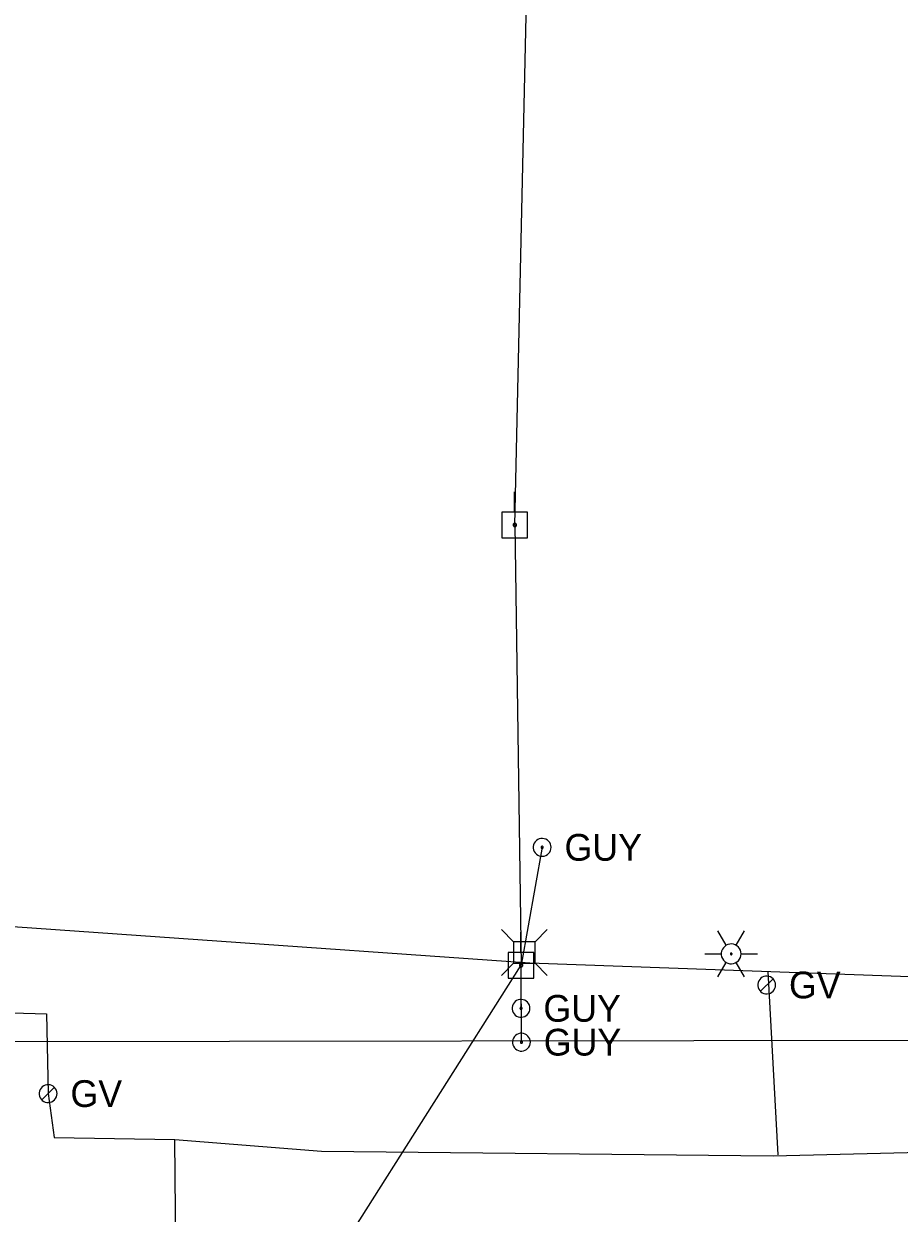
# Model space of a CAD drawing. Extents: x 596028 to 606371, y 330010 to 403088.
# Drawn here: x 604484.3 to 604610.3, y 349950.1 to 350121.3 of the extents above; entities that cross this region are included whole.
import ezdxf

# ---------------------------------------------------------------- set-up
doc = ezdxf.new("R2010")
doc.units = 0
for name, color, linetype in [('E_LTG', 7, 'Continuous'), ('E_UTL_EGuyWire', 7, 'Continuous'), ('E_UTL_EPowerPole', 7, 'Continuous'), ('E_UTL_G', 7, 'Continuous'), ('E_UTL_G_UG', 7, 'Continuous'), ('E_UTL_Overhead', 7, 'Continuous'), ('E_UTL_SAN_UG', 7, 'Continuous'), ('E_UTL_T', 7, 'Continuous')]:
    doc.layers.add(name, color=color, linetype=linetype)

# ---------------------------------------------------------------- blocks, each defined once
blk = doc.blocks.new('ACAD_PROXY_ENTITY_15')
at = {"layer": 'E_LTG'}
for points in [[(1843663.8, 1030159.59), (1843660.17, 1030165.87)], [(1843668.16, 1030159.59), (1843671.79, 1030165.87)], [(1843670.34, 1030155.82), (1843670.26, 1030156.64), (1843670.02, 1030157.44), (1843669.64, 1030158.17), (1843669.13, 1030158.82), (1843668.51, 1030159.36), (1843667.79, 1030159.78), (1843667.01, 1030160.05), (1843666.19, 1030160.17), (1843665.36, 1030160.13), (1843664.56, 1030159.93), (1843663.8, 1030159.59), (1843663.13, 1030159.11), (1843662.56, 1030158.51), (1843662.11, 1030157.81), (1843661.8, 1030157.04), (1843661.64, 1030156.23), (1843661.64, 1030155.4), (1843661.8, 1030154.59), (1843662.11, 1030153.82), (1843662.56, 1030153.12), (1843663.13, 1030152.52), (1843663.8, 1030152.04), (1843664.56, 1030151.7), (1843665.36, 1030151.51), (1843666.19, 1030151.47), (1843667.01, 1030151.58), (1843667.79, 1030151.85), (1843668.51, 1030152.27), (1843669.13, 1030152.81), (1843669.64, 1030153.46), (1843670.02, 1030154.2), (1843670.26, 1030154.99), (1843670.34, 1030155.82)], [(1843670.34, 1030155.82), (1843670.26, 1030156.64), (1843670.02, 1030157.44), (1843669.64, 1030158.17), (1843669.13, 1030158.82), (1843668.51, 1030159.36), (1843667.79, 1030159.78), (1843667.01, 1030160.05), (1843666.19, 1030160.17), (1843665.36, 1030160.13), (1843664.56, 1030159.93), (1843663.8, 1030159.59), (1843663.13, 1030159.11), (1843662.56, 1030158.51), (1843662.11, 1030157.81), (1843661.8, 1030157.04), (1843661.64, 1030156.23), (1843661.64, 1030155.4), (1843661.8, 1030154.59), (1843662.11, 1030153.82), (1843662.56, 1030153.12), (1843663.13, 1030152.52), (1843663.8, 1030152.04), (1843664.56, 1030151.7), (1843665.36, 1030151.51), (1843666.19, 1030151.47), (1843667.01, 1030151.58), (1843667.79, 1030151.85), (1843668.51, 1030152.27), (1843669.13, 1030152.81), (1843669.64, 1030153.46), (1843670.02, 1030154.2), (1843670.26, 1030154.99), (1843670.34, 1030155.82)], [(1843670.34, 1030155.82), (1843670.26, 1030156.64), (1843670.02, 1030157.44), (1843669.64, 1030158.17), (1843669.13, 1030158.82), (1843668.51, 1030159.36), (1843667.79, 1030159.78), (1843667.01, 1030160.05), (1843666.19, 1030160.17), (1843665.36, 1030160.13), (1843664.56, 1030159.93), (1843663.8, 1030159.59), (1843663.13, 1030159.11), (1843662.56, 1030158.51), (1843662.11, 1030157.81), (1843661.8, 1030157.04), (1843661.64, 1030156.23), (1843661.64, 1030155.4), (1843661.8, 1030154.59), (1843662.11, 1030153.82), (1843662.56, 1030153.12), (1843663.13, 1030152.52), (1843663.8, 1030152.04), (1843664.56, 1030151.7), (1843665.36, 1030151.51), (1843666.19, 1030151.47), (1843667.01, 1030151.58), (1843667.79, 1030151.85), (1843668.51, 1030152.27), (1843669.13, 1030152.81), (1843669.64, 1030153.46), (1843670.02, 1030154.2), (1843670.26, 1030154.99), (1843670.34, 1030155.82)], [(1843654.37, 1030155.82), (1843661.62, 1030155.82)], [(1843660.17, 1030145.76), (1843663.8, 1030152.04)], [(1843666.34, 1030155.82), (1843666.34, 1030155.88), (1843666.32, 1030155.95), (1843666.29, 1030156.01), (1843666.24, 1030156.07), (1843666.19, 1030156.11), (1843666.13, 1030156.15), (1843666.07, 1030156.17), (1843666, 1030156.18), (1843665.93, 1030156.18), (1843665.86, 1030156.16), (1843665.8, 1030156.13), (1843665.74, 1030156.09), (1843665.69, 1030156.04), (1843665.66, 1030155.98), (1843665.63, 1030155.92), (1843665.62, 1030155.85), (1843665.62, 1030155.78), (1843665.63, 1030155.71), (1843665.66, 1030155.65), (1843665.69, 1030155.59), (1843665.74, 1030155.54), (1843665.8, 1030155.5), (1843665.86, 1030155.47), (1843665.93, 1030155.46), (1843666, 1030155.45), (1843666.07, 1030155.46), (1843666.13, 1030155.49), (1843666.19, 1030155.52), (1843666.24, 1030155.57), (1843666.29, 1030155.62), (1843666.32, 1030155.68), (1843666.34, 1030155.75), (1843666.34, 1030155.82)], [(1843671.79, 1030145.76), (1843668.16, 1030152.04)], [(1843670.34, 1030155.82), (1843677.59, 1030155.82)]]:
    blk.add_lwpolyline(points, dxfattribs=at)

msp = doc.modelspace()

# ---------------------------------------------------------------- linework, layer by layer
at = {"layer": 'E_UTL_EGuyWire'}
for p in [(604558.91, 350002.78), (604555.87, 349979.6), (604555.92, 349974.73)]:
    msp.add_line(p, (604555.88, 349985.8), dxfattribs=at)
for points in [[(604560.19, 350002.78), (604560.17, 350003.02), (604560.1, 350003.25), (604559.99, 350003.47), (604559.84, 350003.66), (604559.65, 350003.82), (604559.44, 350003.94), (604559.21, 350004.02), (604558.97, 350004.06), (604558.72, 350004.05), (604558.49, 350003.99), (604558.27, 350003.89), (604558.07, 350003.74), (604557.9, 350003.57), (604557.77, 350003.36), (604557.68, 350003.14), (604557.63, 350002.9), (604557.63, 350002.65), (604557.68, 350002.41), (604557.77, 350002.19), (604557.9, 350001.98), (604558.07, 350001.81), (604558.27, 350001.66), (604558.49, 350001.56), (604558.72, 350001.5), (604558.97, 350001.49), (604559.21, 350001.53), (604559.44, 350001.61), (604559.65, 350001.73), (604559.84, 350001.89), (604559.99, 350002.08), (604560.1, 350002.3), (604560.17, 350002.53), (604560.19, 350002.78)], [(604559.07, 350002.78), (604559.06, 350002.81), (604559.06, 350002.83), (604559.04, 350002.86), (604559.02, 350002.89), (604559, 350002.91), (604558.97, 350002.92), (604558.94, 350002.93), (604558.91, 350002.94), (604558.88, 350002.93), (604558.85, 350002.93), (604558.83, 350002.91), (604558.8, 350002.9), (604558.78, 350002.87), (604558.76, 350002.85), (604558.75, 350002.82), (604558.75, 350002.79), (604558.75, 350002.76), (604558.75, 350002.73), (604558.76, 350002.7), (604558.78, 350002.68), (604558.8, 350002.65), (604558.83, 350002.64), (604558.85, 350002.62), (604558.88, 350002.62), (604558.91, 350002.61), (604558.94, 350002.62), (604558.97, 350002.63), (604559, 350002.64), (604559.02, 350002.66), (604559.04, 350002.69), (604559.06, 350002.72), (604559.06, 350002.74), (604559.07, 350002.78)], [(604557.15, 349979.6), (604557.13, 349979.85), (604557.06, 349980.08), (604556.95, 349980.3), (604556.8, 349980.49), (604556.61, 349980.65), (604556.4, 349980.77), (604556.17, 349980.85), (604555.93, 349980.89), (604555.69, 349980.87), (604555.45, 349980.82), (604555.23, 349980.72), (604555.03, 349980.57), (604554.86, 349980.4), (604554.73, 349980.19), (604554.64, 349979.97), (604554.59, 349979.73), (604554.59, 349979.48), (604554.64, 349979.24), (604554.73, 349979.02), (604554.86, 349978.81), (604555.03, 349978.63), (604555.23, 349978.49), (604555.45, 349978.39), (604555.69, 349978.33), (604555.93, 349978.32), (604556.17, 349978.36), (604556.4, 349978.44), (604556.61, 349978.56), (604556.8, 349978.72), (604556.95, 349978.91), (604557.06, 349979.13), (604557.13, 349979.36), (604557.15, 349979.6)], [(604556.03, 349979.6), (604556.03, 349979.63), (604556.02, 349979.66), (604556, 349979.69), (604555.99, 349979.71), (604555.96, 349979.73), (604555.94, 349979.75), (604555.91, 349979.76), (604555.88, 349979.76), (604555.85, 349979.76), (604555.82, 349979.76), (604555.79, 349979.74), (604555.76, 349979.73), (604555.74, 349979.7), (604555.73, 349979.68), (604555.72, 349979.65), (604555.71, 349979.62), (604555.71, 349979.59), (604555.72, 349979.56), (604555.73, 349979.53), (604555.74, 349979.5), (604555.76, 349979.48), (604555.79, 349979.47), (604555.82, 349979.45), (604555.85, 349979.45), (604555.88, 349979.44), (604555.91, 349979.45), (604555.94, 349979.46), (604555.96, 349979.47), (604555.99, 349979.49), (604556, 349979.52), (604556.02, 349979.54), (604556.03, 349979.57), (604556.03, 349979.6)], [(604557.21, 349974.73), (604557.19, 349974.98), (604557.12, 349975.21), (604557, 349975.43), (604556.85, 349975.62), (604556.67, 349975.78), (604556.46, 349975.9), (604556.23, 349975.98), (604555.99, 349976.02), (604555.74, 349976.01), (604555.51, 349975.95), (604555.28, 349975.85), (604555.08, 349975.7), (604554.92, 349975.53), (604554.78, 349975.32), (604554.69, 349975.1), (604554.65, 349974.86), (604554.65, 349974.61), (604554.69, 349974.37), (604554.78, 349974.15), (604554.92, 349973.94), (604555.08, 349973.77), (604555.28, 349973.62), (604555.51, 349973.52), (604555.74, 349973.46), (604555.99, 349973.45), (604556.23, 349973.49), (604556.46, 349973.57), (604556.67, 349973.69), (604556.85, 349973.85), (604557, 349974.04), (604557.12, 349974.26), (604557.19, 349974.49), (604557.21, 349974.73)], [(604556.09, 349974.73), (604556.08, 349974.77), (604556.07, 349974.79), (604556.06, 349974.82), (604556.04, 349974.85), (604556.02, 349974.87), (604555.99, 349974.88), (604555.96, 349974.89), (604555.93, 349974.9), (604555.9, 349974.89), (604555.87, 349974.89), (604555.84, 349974.87), (604555.82, 349974.86), (604555.8, 349974.83), (604555.78, 349974.81), (604555.77, 349974.78), (604555.77, 349974.75), (604555.77, 349974.72), (604555.77, 349974.69), (604555.78, 349974.66), (604555.8, 349974.64), (604555.82, 349974.61), (604555.84, 349974.6), (604555.87, 349974.58), (604555.9, 349974.58), (604555.93, 349974.57), (604555.96, 349974.58), (604555.99, 349974.59), (604556.02, 349974.6), (604556.04, 349974.62), (604556.06, 349974.65), (604556.07, 349974.68), (604556.08, 349974.7), (604556.09, 349974.73)]]:
    msp.add_lwpolyline(points, dxfattribs=at)
at = {"layer": 'E_UTL_EPowerPole'}
for points in [[(604554.93, 350051.02), (604554.93, 350053.93)], [(604556.78, 350051.02), (604553.09, 350051.02)], [(604553.09, 350051.02), (604553.09, 350047.33)], [(604556.78, 350047.33), (604556.78, 350051.02)], [(604555.2, 350049.17), (604555.2, 350049.22), (604555.19, 350049.26), (604555.17, 350049.3), (604555.14, 350049.34), (604555.1, 350049.37), (604555.06, 350049.39), (604555.02, 350049.41), (604554.98, 350049.41), (604554.93, 350049.41), (604554.89, 350049.4), (604554.85, 350049.38), (604554.81, 350049.35), (604554.78, 350049.32), (604554.75, 350049.28), (604554.74, 350049.24), (604554.73, 350049.2), (604554.73, 350049.15), (604554.74, 350049.11), (604554.75, 350049.07), (604554.78, 350049.03), (604554.81, 350048.99), (604554.85, 350048.97), (604554.89, 350048.95), (604554.93, 350048.94), (604554.98, 350048.94), (604555.02, 350048.94), (604555.06, 350048.96), (604555.1, 350048.98), (604555.14, 350049.01), (604555.17, 350049.05), (604555.19, 350049.09), (604555.2, 350049.13), (604555.2, 350049.17)], [(604553.09, 350047.33), (604556.78, 350047.33)], [(604555.85, 349987.65), (604555.85, 349990.56)], [(604557.69, 349987.65), (604554.01, 349987.65)], [(604554.01, 349987.65), (604554.01, 349983.96)], [(604557.69, 349983.96), (604557.69, 349987.65)], [(604556.12, 349985.8), (604556.12, 349985.85), (604556.1, 349985.89), (604556.08, 349985.93), (604556.06, 349985.97), (604556.02, 349986), (604555.98, 349986.02), (604555.94, 349986.04), (604555.89, 349986.04), (604555.85, 349986.04), (604555.81, 349986.03), (604555.76, 349986.01), (604555.73, 349985.98), (604555.7, 349985.95), (604555.67, 349985.91), (604555.65, 349985.87), (604555.65, 349985.83), (604555.65, 349985.78), (604555.65, 349985.74), (604555.67, 349985.69), (604555.7, 349985.66), (604555.73, 349985.62), (604555.76, 349985.6), (604555.81, 349985.58), (604555.85, 349985.57), (604555.89, 349985.57), (604555.94, 349985.57), (604555.98, 349985.59), (604556.02, 349985.61), (604556.06, 349985.64), (604556.08, 349985.68), (604556.1, 349985.72), (604556.12, 349985.76), (604556.12, 349985.8)], [(604554.01, 349983.96), (604557.69, 349983.96)]]:
    msp.add_lwpolyline(points, dxfattribs=at)
at = {"layer": 'E_UTL_G'}
for points in [[(604592.5, 349982.96), (604592.48, 349983.21), (604592.41, 349983.44), (604592.3, 349983.66), (604592.15, 349983.85), (604591.96, 349984.01), (604591.75, 349984.13), (604591.52, 349984.21), (604591.28, 349984.24), (604591.04, 349984.23), (604590.8, 349984.18), (604590.58, 349984.07), (604590.38, 349983.93), (604590.21, 349983.76), (604590.08, 349983.55), (604589.99, 349983.32), (604589.94, 349983.09), (604589.94, 349982.84), (604589.99, 349982.6), (604590.08, 349982.37), (604590.21, 349982.17), (604590.38, 349981.99), (604590.58, 349981.85), (604590.8, 349981.75), (604591.04, 349981.69), (604591.28, 349981.68), (604591.52, 349981.72), (604591.75, 349981.8), (604591.96, 349981.92), (604592.15, 349982.08), (604592.3, 349982.27), (604592.41, 349982.49), (604592.48, 349982.72), (604592.5, 349982.96)], [(604590.31, 349982.06), (604592.13, 349983.87)], [(604489.08, 349967.33), (604489.06, 349967.57), (604488.99, 349967.81), (604488.88, 349968.02), (604488.73, 349968.22), (604488.54, 349968.38), (604488.33, 349968.5), (604488.1, 349968.58), (604487.86, 349968.61), (604487.62, 349968.6), (604487.38, 349968.54), (604487.16, 349968.44), (604486.96, 349968.3), (604486.79, 349968.12), (604486.66, 349967.92), (604486.57, 349967.69), (604486.52, 349967.45), (604486.52, 349967.21), (604486.57, 349966.97), (604486.66, 349966.74), (604486.79, 349966.54), (604486.96, 349966.36), (604487.16, 349966.22), (604487.38, 349966.12), (604487.62, 349966.06), (604487.86, 349966.05), (604488.1, 349966.08), (604488.33, 349966.16), (604488.54, 349966.29), (604488.73, 349966.45), (604488.88, 349966.64), (604488.99, 349966.85), (604489.06, 349967.09), (604489.08, 349967.33)], [(604486.89, 349966.42), (604488.71, 349968.24)]]:
    msp.add_lwpolyline(points, dxfattribs=at)
at = {"layer": 'E_UTL_G_UG'}
for points in [[(604252.85, 349997.07), (604335.69, 349990.44), (604349.27, 349988.73), (604376.12, 349984.81), (604411.24, 349982.02), (604444.79, 349980.04), (604487.55, 349978.81), (604487.8, 349967.33), (604488.65, 349961.03), (604506.03, 349960.73), (604527.14, 349959.03), (604592.13, 349958.39), (604651.99, 349959.87), (604682.48, 349959.49), (604732.67, 349957.01), (604787.08, 349955.9), (604797.56, 349955.68)], [(604592.89, 349958.51), (604591.45, 349984.89)], [(604504.65, 349836.13), (604504.4, 349847.54), (604505.16, 349873.83), (604506.5, 349914.62), (604506.33, 349929.59), (604506.03, 349960.73)]]:
    msp.add_lwpolyline(points, dxfattribs=at)
at = {"layer": 'E_UTL_Overhead'}
for p in [(604554.96, 350049.18), (604462.46, 349838.34)]:
    msp.add_line(p, (604555.88, 349985.8), dxfattribs=at)
for points in [[(604554.96, 350049.17), (604556.91, 350135.45), (604565.59, 350303.76), (604564.9, 350342.72)], [(603181.28, 350035.1), (603329.32, 350032.13), (603487.19, 350051.84), (603697.5, 350053.11), (603794.73, 350045.64), (603986.8, 350030.72), (604135.55, 350019.1), (604355.8, 350001.36), (604456.04, 349993.24), (604557.11, 349986.14), (604654.49, 349982.64), (604747.33, 349981.14), (604855.96, 349980.06), (604969.76, 349979.4), (605156.33, 349975.18)]]:
    msp.add_lwpolyline(points, dxfattribs=at)
at = {"layer": 'E_UTL_SAN_UG'}
msp.add_line((604407.98, 349974.7), (604737.68, 349975.25), dxfattribs=at)
at = {"layer": 'E_UTL_T'}
for points in [[(604554.8, 349989.2), (604553.04, 349990.95)], [(604557.89, 349989.2), (604559.64, 349990.95)], [(604557.89, 349989.2), (604554.8, 349989.2)], [(604554.8, 349989.2), (604554.8, 349986.11)], [(604557.89, 349986.11), (604557.89, 349989.2)], [(604554.8, 349986.11), (604553.04, 349984.35)], [(604554.8, 349986.11), (604557.89, 349986.11)], [(604557.89, 349986.11), (604559.64, 349984.35)]]:
    msp.add_lwpolyline(points, dxfattribs=at)

# ---------------------------------------------------------------- block references
at = {"layer": 'E_LTG', "xscale": 0.32808333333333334, "yscale": 0.32808333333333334}
msp.add_blockref('ACAD_PROXY_ENTITY_15', (-289.97, 12010.49), dxfattribs=at)

# ---------------------------------------------------------------- texts
at = {"layer": 'E_UTL_EGuyWire'}
for p in [(604562.12, 350000.85), (604559.08, 349977.68), (604559.13, 349972.81)]:
    msp.add_text('GUY', height=3.85, dxfattribs=at).set_placement(p)
at = {"layer": 'E_UTL_G'}
for p in [(604594.43, 349981.04), (604491.01, 349965.41)]:
    msp.add_text('GV', height=3.85, dxfattribs=at).set_placement(p)

doc.saveas('drawing.dxf')
